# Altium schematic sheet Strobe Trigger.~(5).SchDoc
size B; Organization: Monterey Bay Aquarium Research Institute; Address1: 7700 Sandholdt Rd; Address2: Moss Landing, CA 95039-9644; CompanyName: MBARI
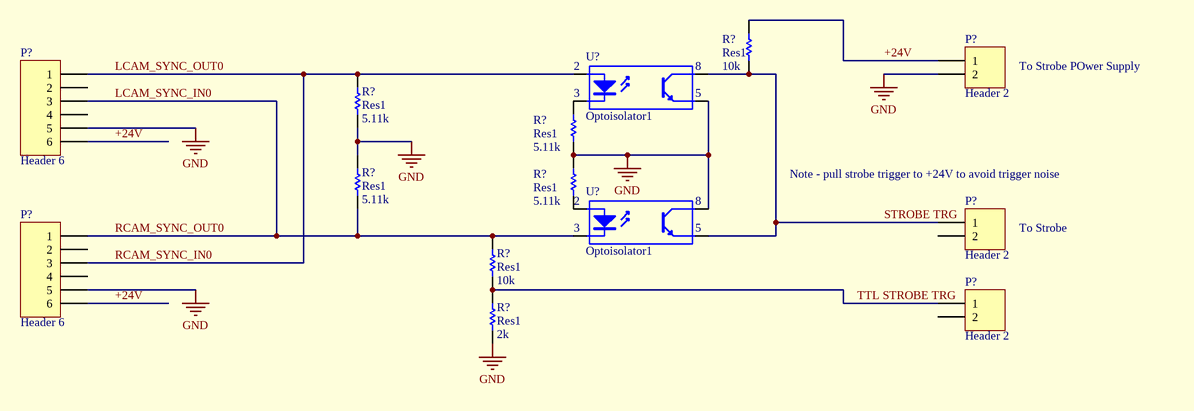
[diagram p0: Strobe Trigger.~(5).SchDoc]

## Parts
(Parts that share a designator on the sheet are numbered #1, #2 ... from top to bottom, then left to right.)
P?#1  Header 2  [HDR1X2]
P?#2  Header 6  [HDR1X6]
P?#3  Header 2  [HDR1X2]
P?#4  Header 6  [HDR1X6]
P?#5  Header 2  [HDR1X2]
R?#1  Res1  value 10k  [AXIAL-0.3]
R?#2  Res1  value 5.11k  [AXIAL-0.3]
R?#3  Res1  value 5.11k  [AXIAL-0.3]
R?#4  Res1  value 5.11k  [AXIAL-0.3]
R?#5  Res1  value 5.11k  [AXIAL-0.3]
R?#6  Res1  value 10k  [AXIAL-0.3]
R?#7  Res1  value 2k  [AXIAL-0.3]
U?#1  Optoisolator1  [DIP-4]
U?#2  Optoisolator1  [DIP-4]

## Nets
GND: P?#1.2 P?#2.5 P?#4.5 R?#2.1 R?#3.1 R?#4.2 R?#5.2 R?#7.1 U?#1.3(E) U?#2.4(C)
+24V: P?#1.1 P?#2.6 P?#4.6 R?#1.2
LCAM_SYNC_IN0: P?#2.3 P?#4.1 R?#4.1 R?#6.2 U?#2.2(K)  [also labelled RCAM_SYNC_OUT0]
LCAM_SYNC_OUT0: P?#2.1 P?#4.3 R?#2.2 U?#1.1(A)  [also labelled RCAM_SYNC_IN0]
STROBE TRG: P?#3.1 R?#1.1 U?#1.4(C) U?#2.3(E)
TTL STROBE TRG: P?#5.1 R?#6.1 R?#7.2
NetR?#3_2: R?#3.2 U?#1.2(K)
NetR?#5_1: R?#5.1 U?#2.1(A)

Not connected (* = marked no-connect by the designer): P?#2 2 4; P?#3 2; P?#4 2 4; P?#5 2

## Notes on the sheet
- (near U?#1) 2
- (near U?#1) 8
- To Strobe POwer Supply
- 3
- (near U?#1) 5
- (near R?#5) 2
- (near U?#2) 8
- (near P?#3) Note - pull strobe trigger to +24V to avoid trigger noise
- (near U?#2) 3
- (near U?#2) 5
- To Strobe

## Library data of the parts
P?#1 P?#3 P?#5 = Header 2: Header, 2-Pin
P?#2 P?#4 = Header 6: Header, 6-Pin
R?#1-R?#7 = Res1: Resistor
U?#1 U?#2 = Optoisolator1: 4-Pin Phototransistor Optocoupler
